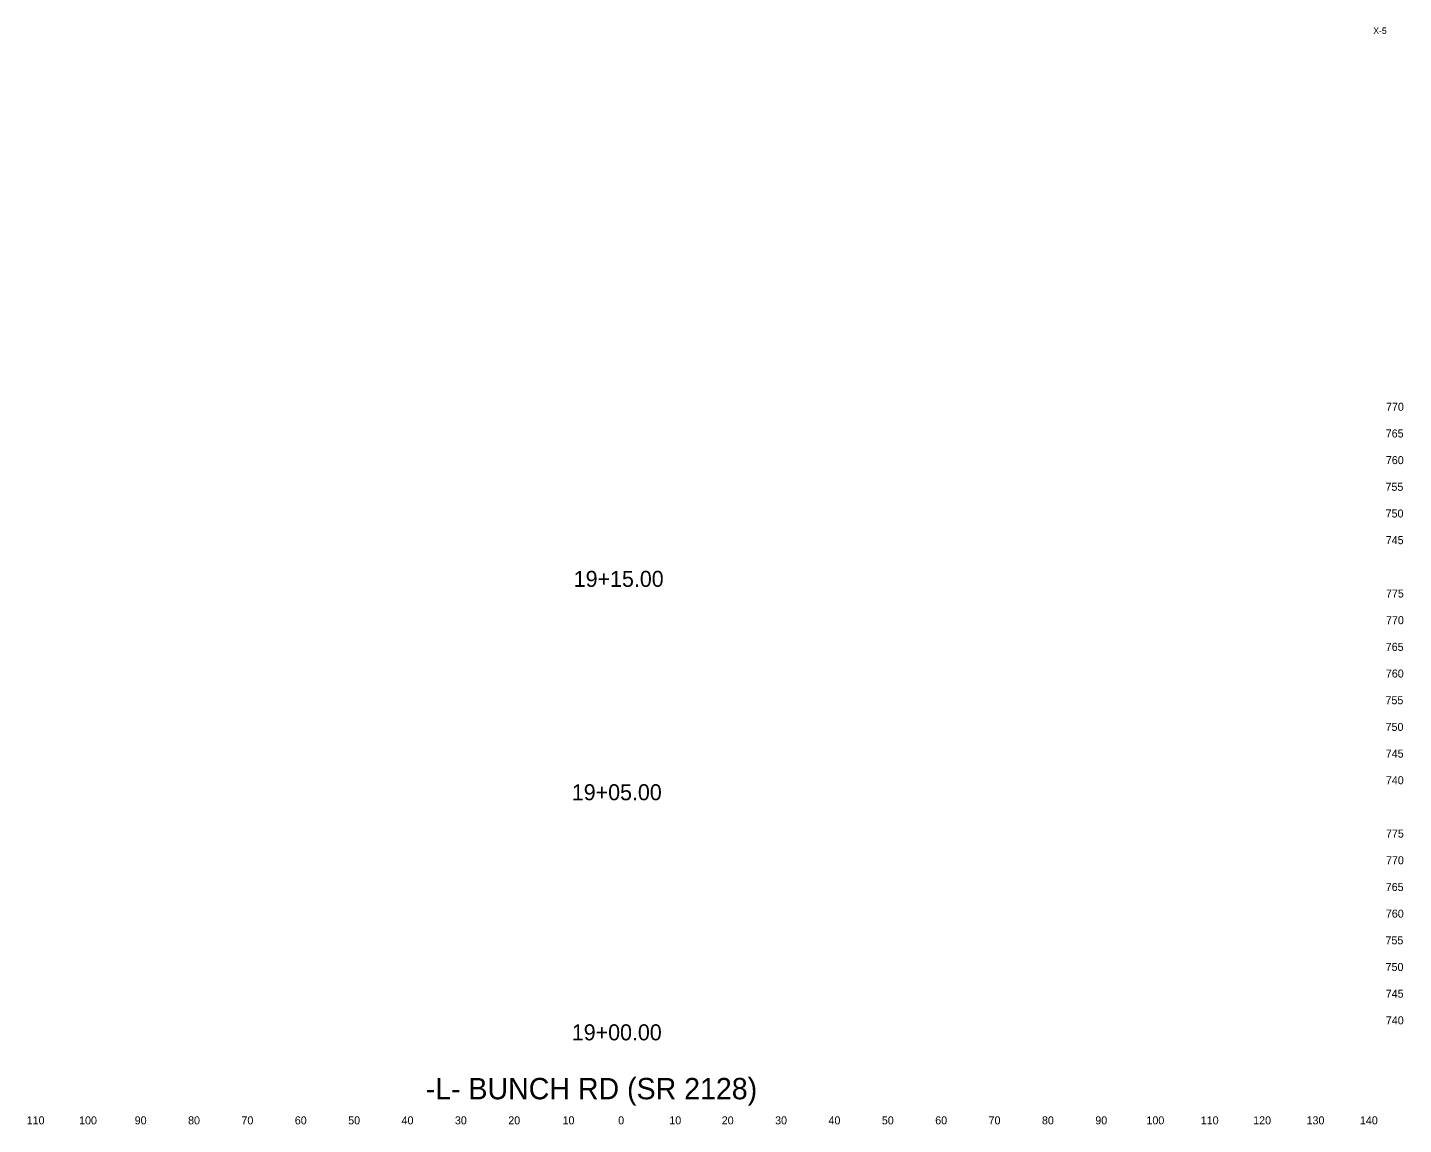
# Model space of a CAD drawing. Extents: x 2473106 to 2475402, y 633617 to 633851.
# Drawn here: x 2475144.5 to 2475402.3, y 633618.8 to 633824.4 of the extents above; entities that cross this region are included whole.
import ezdxf

# ---------------------------------------------------------------- set-up
doc = ezdxf.new("R2010")
doc.units = 0
for name, color, linetype in [('Exist Cross Section Cell', 7, 'Continuous'), ('Exist XS Center Line Elevation Label', 7, 'Continuous'), ('Exist XS Ground Line', 7, 'Continuous'), ('Prop XS SE Text', 7, 'Continuous'), ('Scratch_Level_5', 7, 'Continuous')]:
    doc.layers.add(name, color=color, linetype=linetype)

msp = doc.modelspace()

# ---------------------------------------------------------------- texts
at = {"layer": 'Exist Cross Section Cell'}
for s, p in [('110', (2475144.31, 633618.82)), ('100', (2475154.13, 633618.82)), ('90', (2475164.55, 633618.82)), ('80', (2475174.55, 633618.82)), ('70', (2475184.55, 633618.82)), ('60', (2475194.55, 633618.82)), ('50', (2475204.55, 633618.82)), ('40', (2475214.55, 633618.82)), ('30', (2475224.55, 633618.82)), ('20', (2475234.55, 633618.82)), ('10', (2475244.73, 633618.82)), ('0', (2475255.14, 633618.82)), ('0', (2475255.14, 633618.82)), ('10', (2475264.73, 633618.82)), ('20', (2475274.55, 633618.82)), ('30', (2475284.55, 633618.82)), ('40', (2475294.55, 633618.82)), ('50', (2475304.55, 633618.82)), ('60', (2475314.55, 633618.82)), ('70', (2475324.55, 633618.82)), ('80', (2475334.55, 633618.82)), ('90', (2475344.55, 633618.82)), ('100', (2475354.13, 633618.82)), ('110', (2475364.31, 633618.82)), ('120', (2475374.13, 633618.82)), ('130', (2475384.13, 633618.82)), ('140', (2475394.13, 633618.82))]:
    msp.add_text(s, height=1.5, dxfattribs=at).set_placement(p)
at = {"layer": 'Exist XS Center Line Elevation Label'}
for s, p in [('19+15.00', (2475246.82, 633719.57)), ('19+05.00', (2475246.46, 633679.57)), ('19+00.00', (2475246.46, 633634.57))]:
    msp.add_text(s, height=3, dxfattribs=at).set_placement(p)
at = {"layer": 'Exist XS Ground Line'}
for s, p in [('770', (2475399.02, 633752.57)), ('765', (2475398.97, 633747.57)), ('760', (2475398.99, 633742.57)), ('755', (2475398.92, 633737.57)), ('750', (2475398.94, 633732.57)), ('745', (2475398.97, 633727.57)), ('775', (2475399.01, 633717.57)), ('770', (2475399.02, 633712.57)), ('765', (2475398.97, 633707.57)), ('760', (2475398.99, 633702.57)), ('755', (2475398.92, 633697.57)), ('750', (2475398.94, 633692.57)), ('745', (2475398.97, 633687.57)), ('740', (2475398.99, 633682.57)), ('775', (2475399.01, 633672.57)), ('770', (2475399.02, 633667.57)), ('765', (2475398.97, 633662.57)), ('760', (2475398.99, 633657.57)), ('755', (2475398.92, 633652.57)), ('750', (2475398.94, 633647.57)), ('745', (2475398.97, 633642.57)), ('740', (2475398.99, 633637.57))]:
    msp.add_text(s, height=1.5, dxfattribs=at).set_placement(p)
at = {"layer": 'Prop XS SE Text'}
msp.add_text('X-5', height=1.2, dxfattribs=at).set_placement((2475396.64, 633823.21))
at = {"layer": 'Scratch_Level_5'}
msp.add_text('-L- BUNCH RD (SR 2128)', height=4, dxfattribs=at).set_placement((2475219.07, 633623.52))

doc.saveas('drawing.dxf')
